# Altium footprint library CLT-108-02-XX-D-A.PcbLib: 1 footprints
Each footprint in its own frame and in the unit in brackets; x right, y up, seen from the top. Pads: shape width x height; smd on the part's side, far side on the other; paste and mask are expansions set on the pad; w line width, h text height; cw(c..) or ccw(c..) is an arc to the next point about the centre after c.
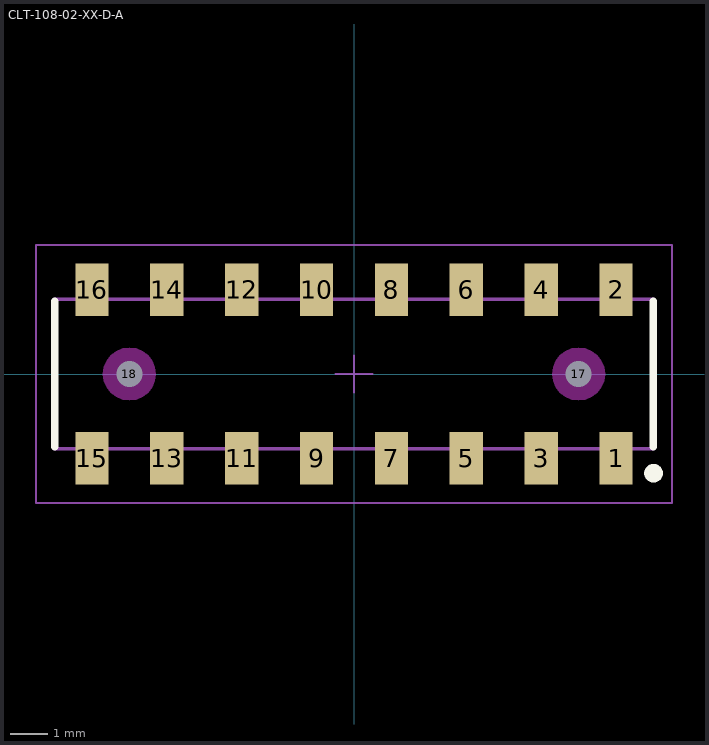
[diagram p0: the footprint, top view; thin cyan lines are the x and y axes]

## CLT-108-02-XX-D-A [mm] "2.00mm pitch, 16 pin, header; low profile, w/alignment pins"
height 2.13
pads (18):
  rect 0.89x1.4 smd mask+0: 1(7,-2.25) 2(7,2.25) 3(5,-2.25) 4(5,2.25) 5(3,-2.25) 6(3,2.25) 7(1,-2.25) 8(1,2.25) 9(-1,-2.25) 10(-1,2.25) 11(-3,-2.25) 12(-3,2.25) 13(-5,-2.25) 14(-5,2.25) 15(-7,-2.25) 16(-7,2.25)
  round 0.5 hole 0.7 unplated mask+0: 17(6,0) 18(-6,0)
Top Overlay:
  circle w0.25: c8,-2.65 r0.125
  lines w0.2: -8,-1.95 -8,1.95 ; 8,-1.95 8,1.95
Keep-Out Layer:
  pour cut-out: -5.294,0 -5.318,0.183 -5.389,0.353 -5.501,0.499 -5.647,0.611 -5.817,0.682 -6,0.706 -6.183,0.682 -6.353,0.611 -6.499,0.499 -6.611,0.353 -6.682,0.183 -6.706,0 -6.682,-0.183 -6.611,-0.353 -6.499,-0.499 -6.353,-0.611 -6.183,-0.682 -6,-0.706 -5.817,-0.682 -5.647,-0.611 -5.501,-0.499 -5.389,-0.353 -5.318,-0.183
  pour cut-out: 6.706,0 6.682,0.183 6.611,0.353 6.499,0.499 6.353,0.611 6.183,0.682 6,0.706 5.817,0.682 5.647,0.611 5.501,0.499 5.389,0.353 5.318,0.183 5.294,0 5.318,-0.183 5.389,-0.353 5.501,-0.499 5.647,-0.611 5.817,-0.682 6,-0.706 6.183,-0.682 6.353,-0.611 6.499,-0.499 6.611,-0.353 6.682,-0.183
Mechanical 12:
  lines w0.001: -8,-2 8,-2 8,2 -8,2 -8,-2
Mechanical 13:
  lines w0.1: -8,-2 8,-2 8,2 -8,2 -8,-2
  text ".Designator" at 0.254,0.254 h1.52
Mechanical 15:
  lines w0.05: -0.5,0 0.5,0 ; 0,-0.5 0,0.5 ; -8.5,-3.45 8.5,-3.45 8.5,3.45 -8.5,3.45 -8.5,-3.45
